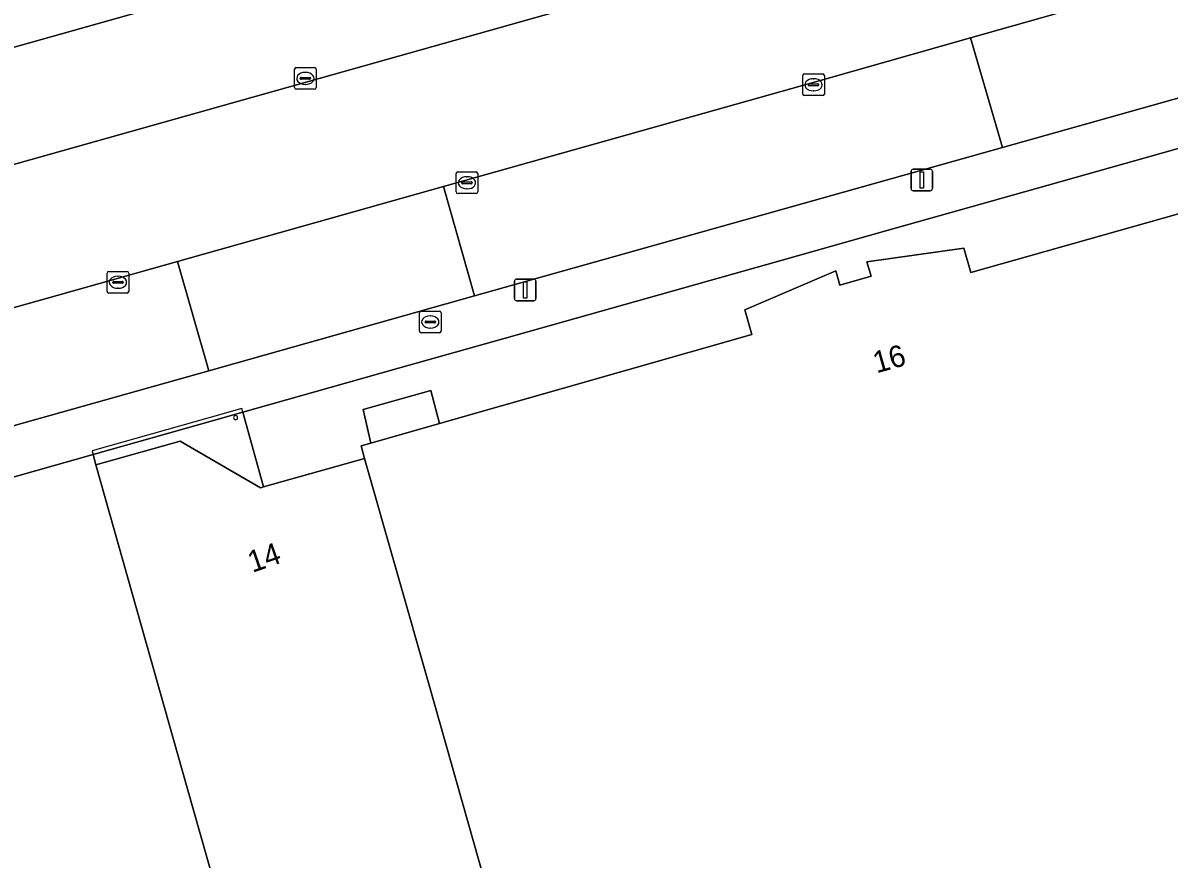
# Model space of a CAD drawing. Extents: x 159680 to 160786, y 387323 to 388340.
# Drawn here: x 159915.5 to 159968.5, y 388088.3 to 388126.9 of the extents above; entities that cross this region are included whole.
import ezdxf

# ---------------------------------------------------------------- set-up
doc = ezdxf.new("R2010")
doc.units = 0
for name, color, linetype in [('IMGEO_Berm_groen', 7, 'Continuous'), ('IMGEO_Brandkraan', 7, 'Continuous'), ('IMGEO_Kolk', 7, 'Continuous'), ('IMGEO_Lichtmast', 7, 'Continuous'), ('IMGEO_Pand', 7, 'Continuous'), ('IMGEO_Pand_nummerreeks', 7, 'Continuous'), ('IMGEO_Pand_overbouw', 7, 'Continuous'), ('IMGEO_Parkeervlak_open', 7, 'Continuous'), ('IMGEO_Rijbaan_lokaal_gesloten', 7, 'Continuous'), ('IMGEO_Voetpad_open', 7, 'Continuous')]:
    doc.layers.add(name, color=color, linetype=linetype)

msp = doc.modelspace()

# ---------------------------------------------------------------- linework, layer by layer
at = {"layer": 'IMGEO_Berm_groen'}
msp.add_lwpolyline([(159890.571, 388118.912), (159957.895, 388137.862)], dxfattribs=at)
at = {"layer": 'IMGEO_Brandkraan'}
for p, q in [((159933.861, 388112.687), (159933.861, 388113.539)), ((159933.936, 388113.613), (159934.788, 388113.613)), ((159934.12, 388113.107), (159934.12, 388113.119)), ((159934.163, 388113.156), (159934.561, 388113.156)), ((159934.349, 388113.393), (159934.374, 388113.393)), ((159934.604, 388113.119), (159934.604, 388113.107)), ((159934.862, 388113.539), (159934.862, 388112.687)), ((159934.788, 388112.613), (159933.936, 388112.613)), ((159934.558, 388113.07), (159934.16, 388113.07)), ((159934.372, 388112.833), (159934.347, 388112.833))]:
    msp.add_line(p, q, dxfattribs=at)
for points in [[(159933.861, 388112.687), (159933.861, 388113.539)], [(159933.936, 388113.613), (159934.788, 388113.613)], [(159934.862, 388113.539), (159934.862, 388112.687)], [(159934.788, 388112.613), (159933.936, 388112.613)]]:
    msp.add_lwpolyline(points, dxfattribs=at)
for centre, radius, start, end in [((159933.938, 388113.537), 0.0765, 91.552, 178.448), ((159933.938, 388113.537), 0.0765, 91.552, 178.448), ((159934.16, 388113.116), 0.0403, 85.8775, 175.7526), ((159934.565, 388113.118), 0.0386, 1.7309, 96.639), ((159934.786, 388113.537), 0.0765, 1.552, 88.448), ((159934.786, 388113.537), 0.0765, 1.552, 88.448), ((159933.938, 388112.689), 0.0765, 181.552, 268.448), ((159933.938, 388112.689), 0.0765, 181.552, 268.448), ((159934.157, 388113.106), 0.0366, 178.938, 274.7102), ((159934.561, 388113.113), 0.043, 264.8664, 352.4533), ((159934.786, 388112.689), 0.0765, 271.552, 358.448), ((159934.786, 388112.689), 0.0765, 271.552, 358.448)]:
    msp.add_arc(centre, radius, start, end, dxfattribs=at)
for centre, major_axis, ratio, start_param, end_param in [((159934.348, 388113.113), (-0.387, 0.002), 0.722429, 4.712389, 7.853982), ((159934.373, 388113.113), (-0.39, 0.002), 0.717154, 1.570796, 4.712389)]:
    msp.add_ellipse(centre, major_axis=major_axis, ratio=ratio, start_param=start_param, end_param=end_param, dxfattribs=at)
at = {"layer": 'IMGEO_Kolk'}
for p, q in [((159928.086, 388123.946), (159928.086, 388124.798)), ((159928.161, 388124.872), (159929.013, 388124.872)), ((159929.087, 388124.798), (159929.087, 388123.946)), ((159928.345, 388124.366), (159928.345, 388124.378)), ((159928.783, 388124.329), (159928.385, 388124.329)), ((159928.388, 388124.415), (159928.786, 388124.415)), ((159928.574, 388124.652), (159928.599, 388124.652)), ((159928.829, 388124.378), (159928.829, 388124.366)), ((159951.576, 388123.649), (159951.576, 388124.501)), ((159951.651, 388124.575), (159952.503, 388124.575)), ((159952.064, 388124.355), (159952.089, 388124.355)), ((159952.577, 388124.501), (159952.577, 388123.649)), ((159929.013, 388123.872), (159928.161, 388123.872)), ((159928.597, 388124.092), (159928.572, 388124.092)), ((159951.835, 388124.069), (159951.835, 388124.081)), ((159952.273, 388124.032), (159951.875, 388124.032)), ((159951.878, 388124.118), (159952.276, 388124.118)), ((159952.087, 388123.795), (159952.062, 388123.795)), ((159952.319, 388124.081), (159952.319, 388124.069)), ((159952.503, 388123.575), (159951.651, 388123.575)), ((159935.629, 388120.047), (159936.481, 388120.047)), ((159935.554, 388119.121), (159935.554, 388119.973)), ((159935.813, 388119.541), (159935.813, 388119.553)), ((159936.251, 388119.504), (159935.853, 388119.504)), ((159935.856, 388119.59), (159936.254, 388119.59)), ((159936.042, 388119.827), (159936.067, 388119.827)), ((159936.297, 388119.553), (159936.297, 388119.541)), ((159936.555, 388119.973), (159936.555, 388119.121)), ((159936.481, 388119.047), (159935.629, 388119.047)), ((159936.065, 388119.267), (159936.04, 388119.267)), ((159919.423, 388114.522), (159919.423, 388115.374)), ((159919.498, 388115.448), (159920.35, 388115.448)), ((159920.424, 388115.374), (159920.424, 388114.522)), ((159919.682, 388114.942), (159919.682, 388114.954)), ((159920.12, 388114.905), (159919.722, 388114.905)), ((159919.725, 388114.991), (159920.123, 388114.991)), ((159919.911, 388115.228), (159919.936, 388115.228)), ((159920.166, 388114.954), (159920.166, 388114.942)), ((159920.35, 388114.448), (159919.498, 388114.448)), ((159919.934, 388114.668), (159919.909, 388114.668))]:
    msp.add_line(p, q, dxfattribs=at)
for points in [[(159928.086, 388123.946), (159928.086, 388124.798)], [(159928.161, 388124.872), (159929.013, 388124.872)], [(159929.087, 388124.798), (159929.087, 388123.946)], [(159951.576, 388123.649), (159951.576, 388124.501)], [(159951.651, 388124.575), (159952.503, 388124.575)], [(159952.577, 388124.501), (159952.577, 388123.649)], [(159929.013, 388123.872), (159928.161, 388123.872)], [(159952.503, 388123.575), (159951.651, 388123.575)], [(159935.629, 388120.047), (159936.481, 388120.047)], [(159935.554, 388119.121), (159935.554, 388119.973)], [(159936.555, 388119.973), (159936.555, 388119.121)], [(159936.481, 388119.047), (159935.629, 388119.047)], [(159919.423, 388114.522), (159919.423, 388115.374)], [(159919.498, 388115.448), (159920.35, 388115.448)], [(159920.424, 388115.374), (159920.424, 388114.522)], [(159920.35, 388114.448), (159919.498, 388114.448)]]:
    msp.add_lwpolyline(points, dxfattribs=at)
for centre, radius, start, end in [((159928.163, 388124.796), 0.0765, 91.552, 178.448), ((159928.163, 388124.796), 0.0765, 91.552, 178.448), ((159929.011, 388124.796), 0.0765, 1.552, 88.448), ((159929.011, 388124.796), 0.0765, 1.552, 88.448), ((159928.385, 388124.375), 0.0403, 85.8775, 175.7526), ((159928.382, 388124.365), 0.0366, 178.938, 274.7102), ((159928.786, 388124.372), 0.043, 264.8664, 352.4533), ((159928.79, 388124.377), 0.0386, 1.7309, 96.639), ((159951.653, 388124.499), 0.0765, 91.552, 178.448), ((159951.653, 388124.499), 0.0765, 91.552, 178.448), ((159952.501, 388124.499), 0.0765, 1.552, 88.448), ((159952.501, 388124.499), 0.0765, 1.552, 88.448), ((159928.163, 388123.948), 0.0765, 181.552, 268.448), ((159928.163, 388123.948), 0.0765, 181.552, 268.448), ((159929.011, 388123.948), 0.0765, 271.552, 358.448), ((159929.011, 388123.948), 0.0765, 271.552, 358.448), ((159951.875, 388124.078), 0.0403, 85.8775, 175.7526), ((159951.872, 388124.068), 0.0366, 178.938, 274.7102), ((159952.276, 388124.075), 0.043, 264.8664, 352.4533), ((159952.28, 388124.08), 0.0386, 1.7309, 96.639), ((159951.653, 388123.651), 0.0765, 181.552, 268.448), ((159951.653, 388123.651), 0.0765, 181.552, 268.448), ((159952.501, 388123.651), 0.0765, 271.552, 358.448), ((159952.501, 388123.651), 0.0765, 271.552, 358.448), ((159935.631, 388119.971), 0.0765, 91.552, 178.448), ((159935.631, 388119.971), 0.0765, 91.552, 178.448), ((159936.479, 388119.971), 0.0765, 1.552, 88.448), ((159936.479, 388119.971), 0.0765, 1.552, 88.448), ((159935.853, 388119.55), 0.0403, 85.8775, 175.7526), ((159935.85, 388119.54), 0.0366, 178.938, 274.7102), ((159936.254, 388119.547), 0.043, 264.8664, 352.4533), ((159936.258, 388119.552), 0.0386, 1.7309, 96.639), ((159935.631, 388119.123), 0.0765, 181.552, 268.448), ((159935.631, 388119.123), 0.0765, 181.552, 268.448), ((159936.479, 388119.123), 0.0765, 271.552, 358.448), ((159936.479, 388119.123), 0.0765, 271.552, 358.448), ((159919.5, 388115.372), 0.0765, 91.552, 178.448), ((159919.5, 388115.372), 0.0765, 91.552, 178.448), ((159920.348, 388115.372), 0.0765, 1.552, 88.448), ((159920.348, 388115.372), 0.0765, 1.552, 88.448), ((159919.722, 388114.951), 0.0403, 85.8775, 175.7526), ((159919.719, 388114.941), 0.0366, 178.938, 274.7102), ((159920.123, 388114.948), 0.043, 264.8664, 352.4533), ((159920.127, 388114.953), 0.0386, 1.7309, 96.639), ((159919.5, 388114.524), 0.0765, 181.552, 268.448), ((159919.5, 388114.524), 0.0765, 181.552, 268.448), ((159920.348, 388114.524), 0.0765, 271.552, 358.448), ((159920.348, 388114.524), 0.0765, 271.552, 358.448)]:
    msp.add_arc(centre, radius, start, end, dxfattribs=at)
for centre, major_axis, ratio, start_param, end_param in [((159928.573, 388124.372), (-0.387, 0.002), 0.722429, 4.712389, 7.853982), ((159928.598, 388124.372), (-0.39, 0.002), 0.717154, 1.570796, 4.712389), ((159952.063, 388124.075), (-0.387, 0.002), 0.722429, 4.712389, 7.853982), ((159952.088, 388124.075), (-0.39, 0.002), 0.717154, 1.570796, 4.712389), ((159936.041, 388119.547), (-0.387, 0.002), 0.722429, 4.712389, 7.853982), ((159936.066, 388119.547), (-0.39, 0.002), 0.717154, 1.570796, 4.712389), ((159919.91, 388114.948), (-0.387, 0.002), 0.722429, 4.712389, 7.853982), ((159919.935, 388114.948), (-0.39, 0.002), 0.717154, 1.570796, 4.712389)]:
    msp.add_ellipse(centre, major_axis=major_axis, ratio=ratio, start_param=start_param, end_param=end_param, dxfattribs=at)
at = {"layer": 'IMGEO_Lichtmast'}
for p, q in [((159956.586, 388119.276), (159956.586, 388120.076)), ((159956.586, 388120.076), (159956.586, 388119.276)), ((159956.686, 388120.176), (159957.476, 388120.176)), ((159957.476, 388120.176), (159956.686, 388120.176)), ((159957.576, 388120.076), (159957.576, 388119.276)), ((159957.576, 388119.276), (159957.576, 388120.076)), ((159957.476, 388119.176), (159956.686, 388119.176)), ((159956.686, 388119.176), (159957.476, 388119.176)), ((159938.253, 388114.193), (159938.253, 388114.993)), ((159938.253, 388114.993), (159938.253, 388114.193)), ((159938.353, 388115.093), (159939.143, 388115.093)), ((159939.143, 388115.093), (159938.353, 388115.093)), ((159939.243, 388114.993), (159939.243, 388114.193)), ((159939.243, 388114.193), (159939.243, 388114.993)), ((159939.143, 388114.093), (159938.353, 388114.093)), ((159938.353, 388114.093), (159939.143, 388114.093))]:
    msp.add_line(p, q, dxfattribs=at)
for points in [[(159957.006, 388120.051), (159957.156, 388120.051), (159957.156, 388119.301), (159957.006, 388119.301), (159957.006, 388120.051)], [(159938.673, 388114.968), (159938.823, 388114.968), (159938.823, 388114.218), (159938.673, 388114.218), (159938.673, 388114.968)]]:
    msp.add_lwpolyline(points, dxfattribs=at)
for centre, start, end in [((159956.686, 388120.076), 90, 180), ((159956.686, 388120.076), 90, 180), ((159957.476, 388120.076), 0, 90), ((159957.476, 388120.076), 360, 90), ((159956.686, 388119.276), 180, 270), ((159956.686, 388119.276), 180, 270), ((159957.476, 388119.276), 270, 0), ((159957.476, 388119.276), 270, 0), ((159938.353, 388114.993), 90, 180), ((159938.353, 388114.993), 90, 180), ((159939.143, 388114.993), 0, 90), ((159939.143, 388114.993), 360, 90), ((159938.353, 388114.193), 180, 270), ((159938.353, 388114.193), 180, 270), ((159939.143, 388114.193), 270, 0), ((159939.143, 388114.193), 270, 0)]:
    msp.add_arc(centre, 0.1, start, end, dxfattribs=at)
at = {"layer": 'IMGEO_Pand'}
for points in [[(159977.726, 388123.346), (159978.446, 388120.795), (159977.127, 388120.422), (159959.347, 388115.395), (159959.027, 388116.529), (159954.546, 388115.888), (159954.734, 388115.225), (159953.294, 388114.818), (159953.106, 388115.482), (159948.902, 388113.675), (159949.225, 388112.529), (159934.794, 388108.418), (159931.62, 388107.514), (159931.161, 388107.383), (159931.325, 388106.806), (159934.312, 388096.325), (159942.735, 388066.58), (160000, 388082.749), (160000.247, 388082.819), (160000, 388083.697), (159993.49, 388106.837), (159988.214, 388126.311)], [(159942.735, 388066.58), (159934.312, 388096.325), (159931.325, 388106.806), (159926.658, 388105.488), (159926.514, 388105.447), (159922.796, 388107.607), (159918.907, 388106.514), (159923.128, 388091.583), (159924.324, 388087.35), (159931.133, 388063.304)], [(159904.613, 388102.991), (159904.776, 388102.414), (159908.978, 388087.576), (159916.983, 388059.308), (159931.133, 388063.304), (159924.324, 388087.35), (159923.128, 388091.583), (159918.907, 388106.514), (159918.772, 388106.993), (159909.131, 388104.268)]]:
    msp.add_lwpolyline(points, close=True, dxfattribs=at)
for start, end in [(0, 180), (180, 0)]:
    msp.add_arc((159925.361, 388108.693), 0.095, start, end, dxfattribs=at)
at = {"layer": 'IMGEO_Pand_overbouw'}
msp.add_lwpolyline([(159922.796, 388107.607), (159926.514, 388105.447), (159926.658, 388105.488), (159925.645, 388109.112), (159924.181, 388108.7), (159918.724, 388107.163), (159918.907, 388106.514)], close=True, dxfattribs=at)
at = {"layer": 'IMGEO_Parkeervlak_open'}
for points in [[(159959.866, 388138.426), (159957.895, 388137.862), (159890.571, 388118.912)], [(159893.564, 388114.331), (159958.725, 388132.684), (159959.853, 388133.046)]]:
    msp.add_lwpolyline(points, dxfattribs=at)
for points in [[(159960.818, 388121.183), (159959.327, 388126.241), (159952.551, 388124.319), (159934.971, 388119.371), (159936.4, 388114.314)], [(159922.67, 388115.909), (159917.152, 388114.356), (159905.738, 388111.152), (159907.177, 388106.094), (159924.119, 388110.86)]]:
    msp.add_lwpolyline(points, close=True, dxfattribs=at)
at = {"layer": 'IMGEO_Rijbaan_lokaal_gesloten'}
for points in [[(159959.853, 388133.046), (159958.725, 388132.684), (159893.564, 388114.331)], [(159883.068, 388107.488), (159883.776, 388104.987), (159886.219, 388105.673), (159903.22, 388110.445), (159905.738, 388111.152), (159917.152, 388114.356), (159922.67, 388115.909), (159934.971, 388119.371), (159952.551, 388124.319), (159959.327, 388126.241), (159972.859, 388130.08), (159972.326, 388132.105)]]:
    msp.add_lwpolyline(points, dxfattribs=at)
at = {"layer": 'IMGEO_Voetpad_open'}
for points in [[(159972.326, 388132.105), (159972.859, 388130.08), (159974.309, 388125), (159971.667, 388124.235), (159960.818, 388121.183), (159936.4, 388114.314), (159924.119, 388110.86), (159907.177, 388106.094), (159904.639, 388105.38), (159887.608, 388100.589), (159885.182, 388099.907), (159883.776, 388104.987), (159883.068, 388107.488)], [(159876.836, 388105.022), (159881.815, 388106.429), (159884.404, 388097.269), (159889.796, 388098.796), (159890.058, 388098.87), (159890.71, 388099.055), (159904.613, 388102.991), (159909.131, 388104.268), (159918.772, 388106.993), (159924.23, 388108.535), (159925.692, 388108.945), (159929.739, 388110.084), (159932.894, 388110.974), (159937.772, 388112.349), (159950.525, 388115.944), (159955.427, 388117.326), (159961.828, 388119.131), (159967.514, 388120.734), (159976.338, 388123.222)], [(159976.338, 388123.222), (159967.514, 388120.734), (159961.828, 388119.131), (159955.427, 388117.326), (159950.525, 388115.944), (159937.772, 388112.349), (159932.894, 388110.974), (159929.739, 388110.084), (159925.692, 388108.945), (159926.658, 388105.488), (159931.325, 388106.806), (159931.161, 388107.383), (159931.62, 388107.514), (159931.251, 388109.07), (159934.379, 388109.946), (159934.794, 388108.418), (159949.225, 388112.529), (159948.902, 388113.675), (159953.106, 388115.482), (159953.294, 388114.818), (159954.734, 388115.225), (159954.546, 388115.888), (159959.027, 388116.529), (159959.347, 388115.395), (159977.127, 388120.422)]]:
    msp.add_lwpolyline(points, dxfattribs=at)
for points in [[(159974.309, 388125), (159972.859, 388130.08), (159959.327, 388126.241), (159960.818, 388121.183), (159971.667, 388124.235)], [(159934.971, 388119.371), (159922.67, 388115.909), (159924.119, 388110.86), (159936.4, 388114.314)], [(159934.794, 388108.418), (159934.379, 388109.946), (159931.251, 388109.07), (159931.62, 388107.514)], [(159924.23, 388108.535), (159918.772, 388106.993), (159918.907, 388106.514), (159922.796, 388107.607), (159926.514, 388105.447), (159926.658, 388105.488), (159925.692, 388108.945)]]:
    msp.add_lwpolyline(points, close=True, dxfattribs=at)
for start, end in [(0, 180), (180, 0)]:
    msp.add_arc((159925.361, 388108.693), 0.095, start, end, dxfattribs=at)

# ---------------------------------------------------------------- texts
at = {"layer": 'IMGEO_Pand_nummerreeks'}
for s, rotation, p in [('16', 15.8356, (159954.991, 388110.733)), ('14', 19.3054, (159926.136, 388101.513))]:
    msp.add_text(s, height=1, rotation=rotation, dxfattribs=at).set_placement(p)

doc.saveas('drawing.dxf')
